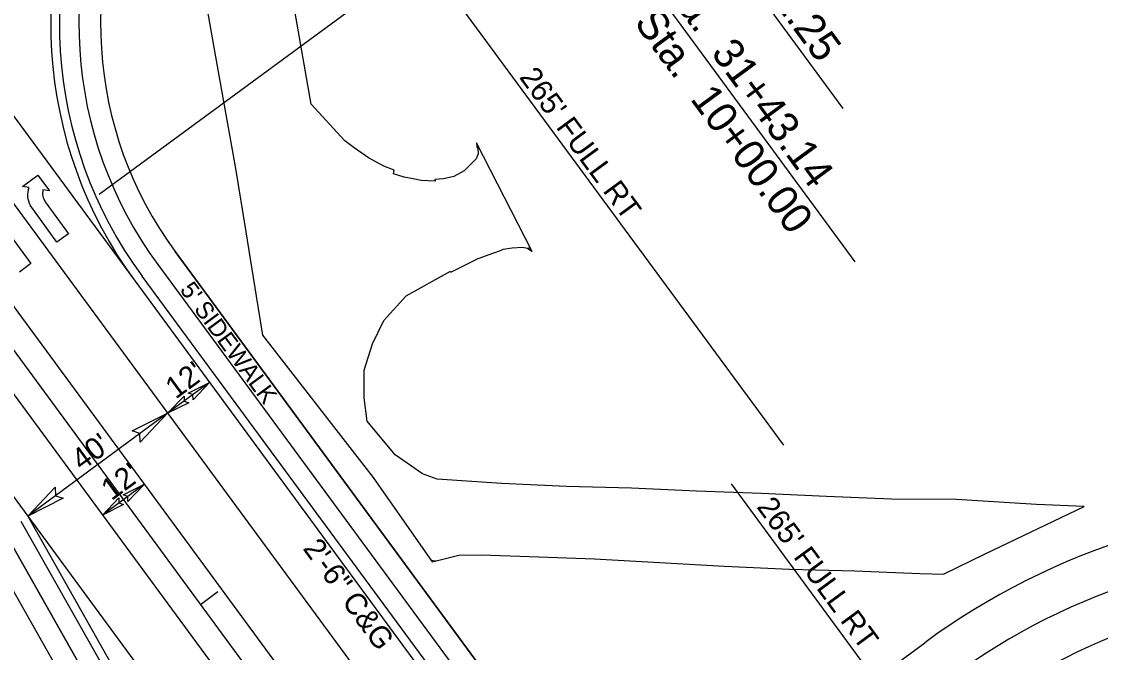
# Model space of a CAD drawing. Extents: x 1762196 to 1766326, y 709922 to 713142.
# Drawn here: x 1763941 to 1764189.7, y 711524.7 to 711670.2 of the extents above; entities that cross this region are included whole.
import ezdxf

# ---------------------------------------------------------------- set-up
doc = ezdxf.new("R2010")
doc.units = 0
for name, color, linetype in [('COGO Default Chain', 7, 'Continuous'), ('Pattern 1', 7, 'Continuous'), ('Pattern 2', 7, 'Continuous'), ('Prop Conc 2ft 6in Curb and Gutter', 7, 'Continuous'), ('Prop Dimension', 7, 'Continuous'), ('Prop EOT', 7, 'Continuous'), ('Prop Horizontal Alignment', 7, 'Continuous'), ('Prop Horizontal Alignment Station Label', 7, 'Continuous'), ('Prop Horizontal Alignment Tick Small', 7, 'Continuous'), ('Prop Lane Arrow CELL', 7, 'Continuous'), ('Prop Lane Lines', 7, 'Continuous'), ('Prop Terminator CELL', 7, 'Continuous')]:
    doc.layers.add(name, color=color, linetype=linetype)

msp = doc.modelspace()

# ---------------------------------------------------------------- linework, layer by layer
at = {"layer": 'COGO Default Chain'}
for p, q in [((1764045.93, 711641.48), (1764046.24, 711641.43)), ((1764058.05, 711618.39), (1764057.95, 711617.69)), ((1763996.54, 711597.87), (1764022.05, 711565.01)), ((1764022.05, 711565.01), (1764035.63, 711545.54)), ((1764163.1, 711547.42), (1764185.9, 711558.36)), ((1764153.53, 711542.71), (1764163.1, 711547.42)), ((1764035.32, 711545.99), (1764036.61, 711545.79))]:
    msp.add_line(p, q, dxfattribs=at)
for points in [[(1764015.54, 711642.67), (1764007.75, 711651.16), (1764003.82, 711673.95), (1763999.2, 711697.97), (1763995.42, 711722.36), (1763990.99, 711747.77)], [(1763978.02, 711705.64), (1763981.24, 711687.38), (1763985.72, 711662.02), (1763990.31, 711636.25)], [(1764031.26, 711633.89), (1764029.22, 711634.32), (1764026.72, 711635.06), (1764026.93, 711635.91), (1764024.5, 711636.79), (1764020.98, 711638.75), (1764017.7, 711641.04), (1764015.54, 711642.67)], [(1764039.87, 711612.58), (1764039.98, 711612.38), (1764046.26, 711615.5), (1764049.89, 711616.86), (1764051.45, 711617.34), (1764052.03, 711617.68), (1764054.1, 711617.98), (1764056.46, 711618.14), (1764057.63, 711617.93), (1764058.71, 711617.11), (1764045.85, 711642.19), (1764045.94, 711641.38), (1764046.2, 711640.84), (1764046.24, 711639.66), (1764045.79, 711638.5), (1764043.01, 711635.77), (1764040.66, 711634.45), (1764038.31, 711633.89), (1764036.27, 711633.75), (1764036.34, 711633.35), (1764033.16, 711633.49), (1764031.26, 711633.89)], [(1763990.31, 711636.25), (1763992.75, 711621.67), (1763995.12, 711606.85), (1763996.54, 711597.87)], [(1764156.53, 711559.93), (1764141.53, 711560.06), (1764126.55, 711560.67), (1764111.57, 711561.35), (1764096.58, 711561.89), (1764081.59, 711562.6), (1764066.6, 711562.98), (1764051.61, 711563.64), (1764036.78, 711564.66), (1764033.42, 711565.86), (1764027.14, 711570.24), (1764020.7, 711578), (1764019.98, 711583.43), (1764020.01, 711589.79), (1764021.88, 711595.85), (1764024.56, 711601.24), (1764029.69, 711606.93), (1764039.87, 711612.58)], [(1764185.9, 711558.36), (1764174.95, 711558.81), (1764156.53, 711559.93)], [(1764035.63, 711545.54), (1764041.79, 711547.09), (1764046.99, 711547.21), (1764058.12, 711546.83), (1764073.11, 711546.28), (1764088.08, 711545.41), (1764103.06, 711544.59), (1764118.04, 711543.92), (1764133.04, 711543.49), (1764148.02, 711542.92), (1764153.53, 711542.71)]]:
    msp.add_lwpolyline(points, dxfattribs=at)
at = {"layer": 'Pattern 1'}
for p, q in [((1764050.49, 711516.41), (1763976.45, 711617.11)), ((1763972.42, 711614.15), (1764046.46, 711513.45)), ((1763986.79, 711464.61), (1763937.22, 711552.29)), ((1763933.19, 711549.33), (1763982.76, 711461.65))]:
    msp.add_line(p, q, dxfattribs=at)
for radius in [93.5, 93.5, 88.5]:
    msp.add_arc((1764047.75, 711669.54), radius, 150.9237, 216.325, dxfattribs=at)
at = {"layer": 'Pattern 2'}
for p, q in [((1763976.45, 711617.11), (1764050.49, 711516.41)), ((1763972.42, 711614.15), (1764046.46, 711513.45)), ((1763937.22, 711552.29), (1763986.79, 711464.61)), ((1763933.19, 711549.33), (1763982.76, 711461.65))]:
    msp.add_line(p, q, dxfattribs=at)
for radius in [93.5, 88.5]:
    msp.add_arc((1764047.75, 711669.54), radius, 150.9237, 216.325, dxfattribs=at)
at = {"layer": 'Prop Conc 2ft 6in Curb and Gutter'}
for p, q in [((1763968.79, 711611.48), (1764042.83, 711510.78)), ((1763940.85, 711554.95), (1763990.42, 711467.28))]:
    msp.add_line(p, q, dxfattribs=at)
msp.add_arc((1764047.75, 711669.54), 98, 150.9237, 216.325, dxfattribs=at)
at = {"layer": 'Prop Dimension'}
for p, q in [((1764036.11, 711687.05), (1763958.95, 711630.32)), ((1764033.69, 711685.28), (1764116.62, 711572.48)), ((1763984.35, 711586.94), (1763974.69, 711579.83)), ((1763974.69, 711579.83), (1763942.46, 711556.14)), ((1763969.33, 711563.48), (1763959.66, 711556.37)), ((1764104.54, 711563.6), (1764178.58, 711462.89))]:
    msp.add_line(p, q, dxfattribs=at)
at = {"layer": 'Prop EOT'}
for p, q in [((1763884.01, 711635.63), (1763942.46, 711556.14)), ((1763967.18, 711610.3), (1764041.22, 711509.6)), ((1763942.46, 711556.14), (1763992.03, 711468.46)), ((1764111.12, 711498.93), (1764149.2, 711526.93))]:
    msp.add_line(p, q, dxfattribs=at)
for centre, radius, start, end in [((1764047.75, 711669.54), 100, 150.9237, 216.325), ((1764246.35, 711394.8), 164, 88.1325, 126.325), ((1764246.35, 711394.8), 144, 88.1325, 126.325)]:
    msp.add_arc(centre, radius, start, end, dxfattribs=at)
at = {"layer": 'Prop Horizontal Alignment'}
msp.add_line((1763362.47, 712378.73), (1764087.96, 711392.01), dxfattribs=at)
msp.add_arc((1764246.35, 711394.8), 154, 88.1325, 126.325, dxfattribs=at)
at = {"layer": 'Prop Horizontal Alignment Station Label'}
for p, q in [((1764066.76, 711736.58), (1764130.29, 711650.14)), ((1764064.44, 711708.2), (1764133.11, 711614.76))]:
    msp.add_line(p, q, dxfattribs=at)
at = {"layer": 'Prop Horizontal Alignment Tick Small'}
msp.add_line((1763982.27, 711535.76), (1763986.3, 711538.72), dxfattribs=at)
msp.add_line((1763982.27, 711535.76), (1763986.3, 711538.72), dxfattribs=at)
at = {"layer": 'Prop Lane Arrow CELL'}
for p, q in [((1763941.23, 711632.11), (1763944.77, 711634.72)), ((1763944.77, 711634.72), (1763947.44, 711631.1)), ((1763942.69, 711631.87), (1763941.23, 711632.11)), ((1763947.44, 711631.1), (1763945.97, 711631.33)), ((1763949.17, 711619.28), (1763943, 711627.84)), ((1763946.5, 711628.63), (1763951.85, 711621.21)), ((1763934.84, 711625.58), (1763943.18, 711614.34)), ((1763951.85, 711621.21), (1763949.17, 711619.28)), ((1763943.18, 711614.34), (1763940.53, 711612.38))]:
    msp.add_line(p, q, dxfattribs=at)
for centre, radius, start, end in [((1763947.67, 711630.22), 5.25, 161.7658, 207.0775), ((1763949.14, 711630.55), 3.27, 166.0954, 215.7536)]:
    msp.add_arc(centre, radius, start, end, dxfattribs=at)
at = {"layer": 'Prop Lane Lines'}
for p, q in [((1763845.88, 711755.02), (1764104.07, 711403.86)), ((1763887.55, 711718.61), (1763967.18, 711610.3)), ((1763916.53, 711635.29), (1764092.79, 711395.56)), ((1763906.87, 711628.18), (1764083.12, 711388.46)), ((1763942.46, 711556.14), (1764071.85, 711380.16))]:
    msp.add_line(p, q, dxfattribs=at)
at = {"layer": 'Prop Terminator CELL'}
for points in [[(1763979.45, 711584.49), (1763984.35, 711586.94), (1763980.55, 711582.95), (1763980.54, 711584.13)], [(1763979.59, 711582.28), (1763974.69, 711579.83), (1763978.49, 711583.82), (1763978.51, 711582.64)], [(1763966.52, 711575.75), (1763974.69, 711579.83), (1763968.34, 711573.18), (1763968.32, 711575.15)], [(1763950.63, 711560.22), (1763942.46, 711556.14), (1763948.8, 711562.79), (1763948.82, 711560.82)], [(1763964.43, 711561.03), (1763969.33, 711563.48), (1763965.53, 711559.49), (1763965.51, 711560.67)], [(1763964.56, 711558.82), (1763959.66, 711556.37), (1763963.47, 711560.36), (1763963.48, 711559.18)]]:
    msp.add_lwpolyline(points, close=True, dxfattribs=at)

# ---------------------------------------------------------------- texts
at = {"layer": 'Prop Dimension'}
for s, height, rotation, p in [("265' FULL RT", 5, 306.325, (1764055.59, 711657.33)), ("5' SIDEWALK", 4, 306.3161, (1763977.37, 711608.29)), ("12'", 5, 36.325, (1763976.54, 711582.95)), ("40'", 5, 36.325, (1763954.88, 711566.4)), ("12'", 5, 36.325, (1763961.76, 711559.55)), ("265' FULL RT", 5, 306.325, (1764110.3, 711558.23)), ('2\'-6" C&G', 5, 306.2561, (1764005.71, 711548.63))]:
    msp.add_text(s, height=height, rotation=rotation, dxfattribs=at).set_placement(p)
at = {"layer": 'Prop Horizontal Alignment Station Label'}
for s, p in [('-Y2- PC Sta.  10+21.25', (1764067.3, 711738.54)), ('-L- POT Sta.  31+43.14', (1764065.58, 711709.45)), ('-Y2- POT Sta.  10+00.00', (1764057.09, 711703.87))]:
    msp.add_text(s, height=7, rotation=306.3131, dxfattribs=at).set_placement(p)

doc.saveas('drawing.dxf')
